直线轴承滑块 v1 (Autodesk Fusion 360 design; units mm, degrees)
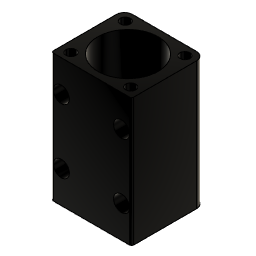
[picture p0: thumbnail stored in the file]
base_feature "基础特征"
extrude "拉伸1" cut of existing geometry blind -0.1
extrude "拉伸2" cut of existing geometry blind -0.1
extrude "拉伸3" cut of existing geometry blind -0.1
extrude "拉伸4" cut of existing geometry blind -0.1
